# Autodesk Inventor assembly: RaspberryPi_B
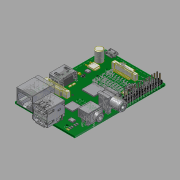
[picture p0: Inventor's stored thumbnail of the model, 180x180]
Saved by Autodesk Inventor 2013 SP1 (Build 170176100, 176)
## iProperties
Created: 2013-01
Part Number: RaspberryPi_B
Document SubType Name: Assembly
Designer: Kevin
Translation Standard: STEP AP214IS
FileName: export0
PreProcessor: Alibre
PostProcessor: Build: 176, Release: 2013 SP1.1 - Date: Tue 10/03/2012
Sent Units: millimeter
Uncertainty: 1e-06
Author: Kevin
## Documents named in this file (23)
- C:\Users\Kevin\Documents\Inventor\Projects\Raspberry_Pi\Raspberry_Pi-STEP\Imported Components\RaspberryPi_B\RaspberryPi_B.iam
- C:\Users\Kevin\Documents\Inventor\Projects\Raspberry_Pi\Raspberry_Pi-STEP\Imported Components\RaspberryPi_B\RaspberryPi_PCB.ipt
- C:\Users\Kevin\Documents\Inventor\Projects\Raspberry_Pi\Raspberry_Pi-STEP\Imported Components\RaspberryPi_B\672982090_USB.ipt
- C:\Users\Kevin\Documents\Inventor\Projects\Raspberry_Pi\Raspberry_Pi-STEP\Imported Components\RaspberryPi_B\5009980900_SD_reader.iam
- C:\Users\Kevin\Documents\Inventor\Projects\Raspberry_Pi\Raspberry_Pi-STEP\Imported Components\RaspberryPi_B\473460001_microUSB.ipt
- C:\Users\Kevin\Documents\Inventor\Projects\Raspberry_Pi\Raspberry_Pi-STEP\Imported Components\RaspberryPi_B\471510001_HDMI.ipt
- C:\Users\Kevin\Documents\Inventor\Projects\Raspberry_Pi\Raspberry_Pi-STEP\Imported Components\RaspberryPi_B\pin_strip-2.54.ipt
- C:\Users\Kevin\Documents\Inventor\Projects\Raspberry_Pi\Raspberry_Pi-STEP\Imported Components\RaspberryPi_B\c-5558065-1-a1-3d.ipt
- C:\Users\Kevin\Documents\Inventor\Projects\Raspberry_Pi\Raspberry_Pi-STEP\Imported Components\RaspberryPi_B\SJ1-3555NG.ipt
- C:\Users\Kevin\Documents\Inventor\Projects\Raspberry_Pi\Raspberry_Pi-STEP\Imported Components\RaspberryPi_B\dsi_conn.ipt
- C:\Users\Kevin\Documents\Inventor\Projects\Raspberry_Pi\Raspberry_Pi-STEP\Imported Components\RaspberryPi_B\raps-holes.ipt
- C:\Users\Kevin\Documents\Inventor\Projects\Raspberry_Pi\Raspberry_Pi-STEP\Imported Components\RaspberryPi_B\parts.ipt
- C:\Users\Kevin\Documents\Inventor\Projects\Raspberry_Pi\Raspberry_Pi-STEP\Imported Components\RaspberryPi_B\electcap.ipt
- C:\Users\Kevin\Documents\Inventor\Projects\Raspberry_Pi\Raspberry_Pi-STEP\Imported Components\RaspberryPi_B\dpack.ipt
- C:\Users\Kevin\Documents\Inventor\Projects\Raspberry_Pi\Raspberry_Pi-STEP\Imported Components\RaspberryPi_B\soic.ipt
- C:\Users\Kevin\Documents\Inventor\Projects\Raspberry_Pi\Raspberry_Pi-STEP\Imported Components\RaspberryPi_B\3-SOT23.ipt
- C:\Users\Kevin\Documents\Inventor\Projects\Raspberry_Pi\Raspberry_Pi-STEP\Imported Components\RaspberryPi_B\3-SOT223.ipt
- C:\Users\Kevin\Documents\Inventor\Projects\Raspberry_Pi\Raspberry_Pi-STEP\Imported Components\RaspberryPi_B\5-SOT323.ipt
- C:\Users\Kevin\Documents\Inventor\Projects\Raspberry_Pi\Raspberry_Pi-STEP\Imported Components\RaspberryPi_B\caps.ipt
- C:\Users\Kevin\Documents\Inventor\Projects\Raspberry_Pi\Raspberry_Pi-STEP\Imported Components\RaspberryPi_B\leds.ipt
- C:\Users\Kevin\Documents\Inventor\Projects\Raspberry_Pi\Raspberry_Pi-STEP\Imported Components\RaspberryPi_B\3-SOT23-a.ipt
- C:\Users\Kevin\Documents\Inventor\Projects\Raspberry_Pi\Raspberry_Pi-STEP\Imported Components\RaspberryPi_B\soic-10.ipt
- C:\Users\Kevin\Documents\Inventor\Projects\Raspberry_Pi\Raspberry_Pi-STEP\Imported Components\RaspberryPi_B\RCJ-044.ipt
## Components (36 placed, 22 different names)
1. RaspberryPi_PCB:1
2. 672982090_USB:1
3. 5009980900_SD_reader:1 [sub-assembly]
4. 473460001_microUSB:1
5. 471510001_HDMI:1
6. pin_strip-2.54:1
7. pin_strip-2.54:2
8. pin_strip-2.54:3
9. pin_strip-2.54:4
10. pin_strip-2.54:5
11. pin_strip-2.54:6
12. pin_strip-2.54:7
13. pin_strip-2.54:8
14. pin_strip-2.54:9
15. pin_strip-2.54:10
16. pin_strip-2.54:11
17. pin_strip-2.54:12
18. pin_strip-2.54:13
19. c-5558065-1-a1-3d:1
20. SJ1-3555NG:1
21. dsi_conn:1
22. dsi_conn:2
23. raps-holes:1
24. parts:1
25. electcap:1
26. dpack:1
27. soic:1
28. 3-SOT23:1
29. 3-SOT223:1
30. 5-SOT323:1
31. caps:1
32. leds:1
33. 3-SOT23-a:1
34. soic-10:1
35. soic-10:2
36. RCJ-044:1
